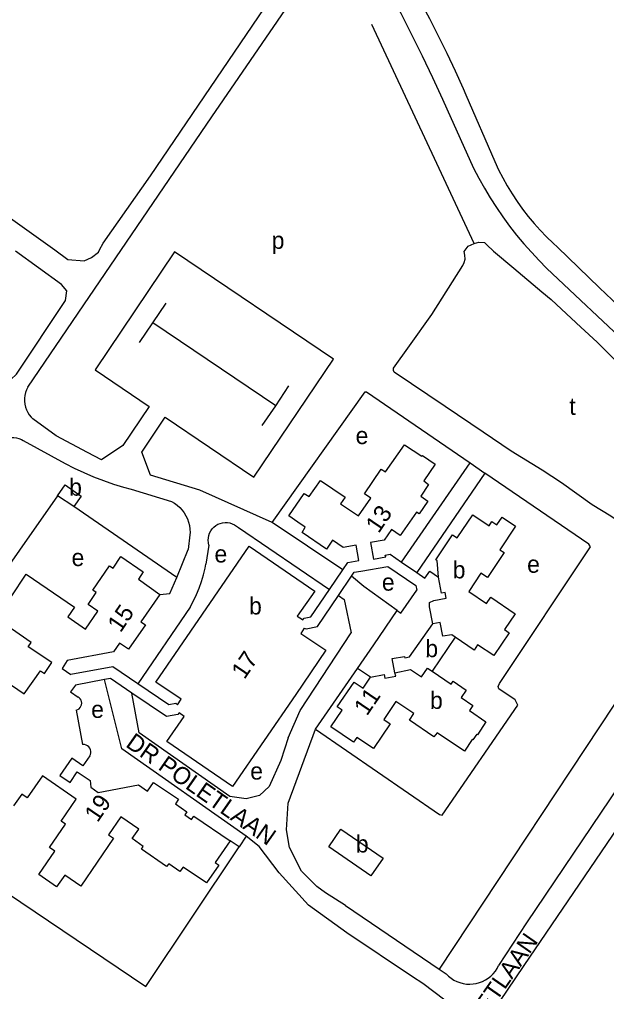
# Model space of a CAD drawing. Extents: x 158142 to 159655, y 385262 to 387204.
# Drawn here: x 159265.7 to 159402.4, y 385994 to 386220.3 of the extents above; entities that cross this region are included whole.
import ezdxf

# ---------------------------------------------------------------- set-up
doc = ezdxf.new("R2010")
doc.units = 0
for name, color, linetype in [('BLT_Basislijn', 7, 'Continuous'), ('BLT_Bebouwing', 7, 'Continuous'), ('BLT_Centroide', 7, 'Continuous'), ('BLT_Huisnummer', 7, 'Continuous'), ('BLT_Onderverdeling_panden', 7, 'Continuous'), ('BLT_Straatnaam_verkleind', 7, 'Continuous')]:
    doc.layers.add(name, color=color, linetype=linetype)

msp = doc.modelspace()

# ---------------------------------------------------------------- linework, layer by layer
at = {"layer": 'BLT_Basislijn'}
for p, q in [((159369.67, 386202.8), (159376.4, 386187.3)), ((159365.25, 386199.55), (159371.45, 386185.69)), ((159280.7, 386153.85), (159310.52, 386197.65)), ((159296.78, 386149.68), (159299.89, 386154.28)), ((159267.69, 386134.69), (159280.7, 386153.85)), ((159293.68, 386145.09), (159296.78, 386149.68)), ((159325.39, 386130.39), (159296.78, 386149.68)), ((159325.39, 386130.39), (159328.49, 386134.99)), ((159322.28, 386125.79), (159325.39, 386130.39)), ((159274.28, 386123.41), (159268.85, 386127.37)), ((159266.61, 386122.3), (159276.35, 386116.91)), ((159354.67, 386093.99), (159370.66, 386117.05)), ((159370.66, 386117.05), (159374.09, 386114.69)), ((159374.09, 386114.69), (159358.23, 386091.55)), ((159291.71, 386110.92), (159301.1, 386108.1)), ((159302.38, 386090.37), (159278.36, 386106.9)), ((159316.7, 386101.99), (159337.91, 386087.59)), ((159305.42, 386100.34), (159305, 386096.93)), ((159309.84, 386097.92), (159309.14, 386093.51)), ((159302.38, 386090.37), (159305, 386096.93)), ((159340.01, 386086.16), (159341.34, 386085.26)), ((159341.34, 386085.26), (159342.96, 386077.47)), ((159305.48, 386083.48), (159293.29, 386065.65)), ((159417.74, 386081.26), (159363.43, 385999.19)), ((159334.65, 386055.1), (159344.46, 386069.2)), ((159417.4, 386059.84), (159383.77, 386009.99)), ((159422.86, 386058.44), (159383.2, 386000)), ((159295.18, 385995.16), (159316.87, 386027.67)), ((159316.87, 386027.67), (159314.77, 386029.04)), ((159341.68, 386014.02), (159363.43, 385999.19)), ((159383.77, 386009.99), (159377.31, 386000)), ((159383.2, 386000), (159360.49, 385966.58)), ((159363.43, 385999.19), (159365.06, 385998.08))]:
    msp.add_line(p, q, dxfattribs=at)
for points in [[(159257.19, 386172.23), (159259.87, 386175.88), (159260.88, 386175.98), (159273.93, 386166.67), (159277.01, 386164.47), (159280.82, 386164.1), (159282.54, 386164.89), (159284.1, 386166.15), (159284.38, 386166.67), (159285.25, 386168.27), (159296.23, 386183.93), (159335.35, 386241.6)], [(159349.8, 386240.06), (159352.21, 386236.24), (159354.56, 386232.37), (159356.84, 386228.47), (159359.05, 386224.52), (159361.19, 386220.54), (159363.26, 386216.52), (159365.26, 386212.46), (159367.18, 386208.37), (159369.04, 386204.25), (159369.67, 386202.8)], [(159310.52, 386197.65), (159328.55, 386223.94), (159339.27, 386239.78)], [(159349.21, 386231.63), (159351.9, 386226.75), (159354.51, 386221.83), (159357.05, 386216.87), (159359.52, 386211.88), (159361.92, 386206.85), (159364.25, 386201.79), (159365.25, 386199.55)], [(159371.61, 386168.13), (159362.91, 386186.76), (159347.77, 386219.17)], [(159371.45, 386185.69), (159372.68, 386183.35), (159373.98, 386181.04), (159375.34, 386178.77), (159376.78, 386176.54), (159378.28, 386174.36), (159379.85, 386172.23), (159381.48, 386170.14), (159383.17, 386168.11), (159384.93, 386166.12), (159386.74, 386164.19), (159388.48, 386162.44)], [(159376.4, 386187.3), (159377.31, 386185.35), (159378.28, 386183.44), (159379.33, 386181.56), (159380.44, 386179.73), (159381.62, 386177.94), (159382.87, 386176.19), (159384.18, 386174.49), (159385.56, 386172.84), (159386.99, 386171.25), (159388.48, 386169.71), (159390.03, 386168.22), (159391.04, 386167.32)], [(159416.11, 386100.81), (159412.56, 386101.79), (159408.57, 386102.44), (159406.6, 386102.92), (159404.9, 386103.62), (159403.46, 386104.7), (159399.06, 386107.3), (159391.98, 386112.43), (159387.43, 386115.36), (159380.2, 386119.83), (159373.69, 386124.24), (159364.83, 386130.24), (159352.95, 386138.24), (159352.82, 386138.61), (159352.79, 386139.15), (159356.55, 386144.3), (159361.74, 386151.63), (159369, 386163.07), (159369.29, 386163.75), (159369.53, 386164.53), (159369.42, 386165.46), (159369.3, 386166.34), (159370.21, 386167.56), (159371.61, 386168.13)], [(159371.61, 386168.13), (159372.66, 386168.47), (159374.01, 386168.39), (159374.55, 386167.84), (159376.09, 386166.41), (159380.84, 386162.43), (159387.34, 386156.94), (159389.57, 386155.12), (159391.96, 386152.89), (159396.48, 386148.66), (159400.23, 386145.16), (159404.79, 386140.58)], [(159242.6, 386136.09), (159245.85, 386133.75), (159249.48, 386132.76), (159254.73, 386132.68), (159259.12, 386133.32), (159260.39, 386133.86), (159262.39, 386135.24), (159265.01, 386137.77), (159276.46, 386154.86), (159276.77, 386157.11), (159275.51, 386158.61), (159264.84, 386166.36)], [(159324.55, 386103.21), (159307.71, 386110.71), (159296.27, 386114.24), (159294.22, 386119.61), (159299.63, 386127.71), (159320.28, 386113.77), (159338.85, 386141.24), (159301.85, 386166.2), (159283.32, 386138.74), (159295.91, 386130.21), (159289.81, 386121.12), (159284.83, 386117.81), (159281.56, 386119.46), (159274.28, 386123.41)], [(159391.04, 386167.32), (159400.79, 386157.88), (159414.04, 386145.26)], [(159408.02, 386143.99), (159395.1, 386156.13), (159388.48, 386162.44)], [(159267.69, 386134.69), (159267.38, 386134.08), (159267.14, 386133.45), (159266.97, 386132.79), (159266.89, 386132.11), (159266.88, 386131.43), (159266.96, 386130.75), (159267.11, 386130.09), (159267.34, 386129.45), (159267.65, 386128.84), (159268.02, 386128.27), (159268.46, 386127.75), (159268.85, 386127.37)], [(159324.55, 386103.21), (159346.2, 386133.6), (159346.52, 386133.64), (159370.66, 386117.05)], [(159260, 386120.43), (159260.3, 386120.96), (159260.67, 386121.44), (159261.09, 386121.87), (159261.57, 386122.24), (159262.09, 386122.55), (159262.65, 386122.78), (159263.23, 386122.94), (159263.83, 386123.02), (159264.44, 386123.02), (159265.04, 386122.94), (159265.62, 386122.78), (159266.18, 386122.55), (159266.61, 386122.3)], [(159276.35, 386116.91), (159278.46, 386115.85), (159280.71, 386114.81), (159282.98, 386113.85), (159285.28, 386112.96), (159287.62, 386112.15), (159289.97, 386111.41), (159291.71, 386110.92)], [(159334.65, 386055.1), (159363.54, 386035.2), (159364.18, 386035.01), (159381.77, 386060.68), (159381.14, 386061.89), (159377.38, 386064.43), (159377.22, 386065.01), (159377.52, 386065.7), (159398.67, 386097.51), (159398.32, 386098.16), (159374.09, 386114.69)], [(159274.62, 386109.39), (159256.83, 386084.07), (159256.42, 386084.07), (159251.48, 386087.44), (159251.1, 386087.39), (159237.9, 386068.19), (159237.9, 386067.62), (159238.66, 386066.64), (159243.79, 386063.26), (159245.06, 386062.05), (159245.09, 386061.56), (159236.59, 386048.38)], [(159301.1, 386108.1), (159301.8, 386107.69), (159302.45, 386107.21), (159303.05, 386106.67), (159303.59, 386106.08), (159304.07, 386105.43), (159304.48, 386104.74), (159304.83, 386104.01), (159305.1, 386103.25), (159305.29, 386102.47), (159305.41, 386101.67), (159305.44, 386100.86), (159305.42, 386100.34)], [(159309.84, 386097.92), (159309.72, 386098.48), (159309.67, 386099.05), (159309.71, 386099.63), (159309.82, 386100.19), (159310.01, 386100.73), (159310.27, 386101.24), (159310.61, 386101.71), (159311, 386102.12), (159311.45, 386102.48), (159311.94, 386102.77), (159312.47, 386102.99), (159313.03, 386103.13), (159313.6, 386103.2), (159314.17, 386103.19), (159314.74, 386103.09), (159315.28, 386102.92), (159315.8, 386102.68), (159316.28, 386102.36), (159316.7, 386101.99)], [(159341.01, 386092.15), (159324.55, 386103.21)], [(159305.48, 386083.48), (159306.24, 386084.92), (159306.93, 386086.39), (159307.55, 386087.9), (159308.1, 386089.44), (159308.56, 386091), (159308.95, 386092.58), (159309.14, 386093.51)], [(159353.67, 386082.67), (159345.93, 386088.26), (159343.07, 386090.66)], [(159298.38, 386086.42), (159300.77, 386086.63), (159302.38, 386090.37)], [(159328.27, 386053.03), (159331.11, 386059.41), (159342.96, 386077.47)], [(159318.51, 386030.13), (159289.58, 386050.48), (159285.52, 386066.6)], [(159328.27, 386053.03), (159326.57, 386047.8), (159323.87, 386041.75), (159321.6, 386039.59), (159318.52, 386038.82), (159314.7, 386039.36), (159293.59, 386054.24), (159291.9, 386063.46)], [(159341.68, 386014.02), (159336.96, 386016.94), (159335, 386018.45), (159331.41, 386022.02), (159328.64, 386027.53), (159327.92, 386031.63), (159328.32, 386037.8), (159334.65, 386055.1)], [(159236.59, 386048.38), (159233.66, 386044.64), (159263.45, 386024.81), (159259.49, 386019.16), (159295.18, 385995.16)], [(159318.51, 386030.13), (159316.87, 386027.67)], [(159326.2, 386021.62), (159321.52, 386027.74), (159318.51, 386030.13)], [(159364.77, 385991.98), (159359.67, 385995.81), (159357.27, 385997.38), (159341.92, 386007.64), (159333.04, 386014.11), (159326.2, 386021.62)], [(159365.06, 385998.08), (159365.62, 385997.54), (159366.22, 385997.06), (159366.87, 385996.64), (159367.56, 385996.3), (159368.29, 385996.03), (159369.03, 385995.83), (159369.8, 385995.71), (159370.57, 385995.68), (159371.34, 385995.72), (159372.1, 385995.84), (159372.84, 385996.04), (159373.57, 385996.32), (159374.25, 385996.67), (159374.9, 385997.08), (159375.5, 385997.57), (159376.05, 385998.11), (159376.54, 385998.71), (159376.97, 385999.35), (159377.31, 386000)]]:
    msp.add_lwpolyline(points, dxfattribs=at)
at = {"layer": 'BLT_Bebouwing'}
for p, q in [((159278.36, 386106.9), (159274.62, 386109.39)), ((159354.67, 386093.99), (159358.23, 386091.55)), ((159337.91, 386087.59), (159341.01, 386092.15)), ((159340.01, 386086.16), (159343.07, 386090.66)), ((159358.23, 386091.55), (159360.15, 386090.24)), ((159331.64, 386080.57), (159331.67, 386080.44)), ((159367.19, 386076.5), (159361.79, 386068.57)), ((159344.46, 386069.2), (159348.23, 386074.72)), ((159277.63, 386063.76), (159279.42, 386062.54)), ((159278.96, 386059.5), (159280.41, 386051.49)), ((159282.08, 386048.83), (159280.47, 386046.49))]:
    msp.add_line(p, q, dxfattribs=at)
for points in [[(159330.54, 386103.29), (159328.43, 386104.75), (159332.03, 386109.98), (159333.19, 386109.21), (159335.8, 386113.01), (159341.54, 386109.07), (159340.47, 386107.55), (159344.67, 386104.72), (159347.56, 386108.88), (159346.06, 386109.9), (159349.99, 386115.64), (159350.99, 386114.96), (159355.38, 386121.31), (159359.43, 386118.64), (159359.56, 386118.8), (159362.52, 386116.78), (159359.88, 386112.88), (159361, 386112.06), (159359.19, 386109.35), (159360.84, 386108.18), (159358.78, 386105.2), (159358.15, 386105.62), (159354.39, 386100.18), (159352.38, 386101.59), (159350.66, 386099.08), (159347.5, 386098.55)], [(159274.62, 386109.39), (159276.38, 386111.95), (159280.1, 386109.33), (159278.36, 386106.9)], [(159363.32, 386090.45), (159362.96, 386094.34), (159362.7, 386094.52), (159366.6, 386100.31), (159367.66, 386099.59), (159371.3, 386104.98), (159375.09, 386102.42), (159375.76, 386103.43), (159376.87, 386102.67), (159378.1, 386104.47), (159381.25, 386102.35), (159377.56, 386096.85), (159378.57, 386096.17), (159374.68, 386090.38), (159373.18, 386091.39), (159370.34, 386087.16), (159374.49, 386084.32), (159375.48, 386085.83), (159381.17, 386081.95), (159378.68, 386078.24), (159379.77, 386077.51), (159376.2, 386072.19), (159372.42, 386074.73), (159371.57, 386073.47), (159367.19, 386076.5)], [(159344.16, 386097.89), (159341.12, 386097.34), (159338.63, 386099.05), (159337.2, 386097.02), (159331.52, 386100.9), (159332.29, 386102.07), (159330.54, 386103.29)], [(159302.53, 386060.76), (159303.35, 386062.02), (159297.45, 386065.99), (159319.25, 386097.72)], [(159319.25, 386097.72), (159334.52, 386087.24), (159330.43, 386081.4), (159331.64, 386080.57)], [(159341.01, 386092.15), (159342.19, 386093.87), (159344.79, 386094.36), (159344.16, 386097.89)], [(159347.5, 386098.55), (159348.15, 386094.69), (159351.04, 386095.2), (159350.92, 386095.61), (159352.04, 386095.79), (159354.67, 386093.99)], [(159263.79, 386085.92), (159267.32, 386091.16), (159278.51, 386083.48), (159276.96, 386081.24), (159281.13, 386078.37), (159283.99, 386082.54), (159281.73, 386084.09), (159283.56, 386086.86), (159282.84, 386087.4), (159286.72, 386093.11), (159287.51, 386092.58), (159289.32, 386095.28), (159294.51, 386091.71), (159293.41, 386090.03), (159298.38, 386086.42)], [(159343.07, 386090.66), (159343.7, 386091.59), (159345.24, 386091.86), (159351.47, 386092.96), (159357.99, 386088.53), (159358.22, 386087.41)], [(159360.15, 386090.24), (159361.26, 386091.86), (159363.32, 386090.45)], [(159298.38, 386086.42), (159294.02, 386080.05), (159295.04, 386079.34), (159291.09, 386073.68), (159289.05, 386075.07), (159287.64, 386073.08), (159276.87, 386071.04), (159275.67, 386069.23), (159277.67, 386067.81)], [(159331.67, 386080.44), (159332, 386080.92), (159333.58, 386081.23), (159337.91, 386087.59)], [(159332.01, 386078.61), (159332.46, 386078.41), (159335.11, 386078.94), (159340.01, 386086.16)], [(159353.67, 386082.67), (159354.56, 386082.06), (159358.22, 386087.41)], [(159348.23, 386074.72), (159353.67, 386082.67)], [(159262.39, 386066.32), (159266.82, 386063.33), (159270.59, 386068.68), (159271.54, 386068.04), (159273.23, 386070.6), (159267.78, 386074.27), (159268.46, 386075.27), (159262.08, 386079.66)], [(159332.01, 386078.61), (159331.22, 386077.34), (159337.1, 386073.46), (159330.05, 386063.16)], [(159293.29, 386065.65), (159287.5, 386069.59), (159277.67, 386067.81)], [(159361.79, 386068.57), (159366.27, 386065.55), (159366.71, 386066.22), (159369.72, 386064.16), (159368.6, 386062.46), (159371.29, 386060.57), (159370.51, 386059.44), (159374.35, 386056.76), (159372.36, 386053.78), (159372.22, 386053.88), (159371.28, 386052.58), (159371.17, 386052.65), (159369.38, 386049.95), (159362.99, 386054.24), (159362.24, 386053.27), (159356.52, 386057.16), (159357.54, 386058.69), (159353.37, 386061.54), (159350.55, 386057.34), (159352.05, 386056.33), (159348.13, 386050.57), (159344.31, 386053.12), (159343.5, 386052), (159338.23, 386055.58), (159340.9, 386059.52), (159339.73, 386060.28), (159343.67, 386066.03), (159345.73, 386064.62), (159347.45, 386067.15)], [(159347.45, 386067.15), (159344.46, 386069.2)], [(159353.17, 386068.21), (159356.81, 386068.93), (159359.38, 386067.23), (159360.76, 386069.27), (159361.79, 386068.57)], [(159285.52, 386066.6), (159278.77, 386065.34), (159277.63, 386063.76)], [(159291.9, 386063.46), (159286.91, 386066.86), (159285.52, 386066.6)], [(159302.92, 386058.89), (159302.64, 386058.51), (159299.95, 386057.98), (159291.9, 386063.46)], [(159302.53, 386060.76), (159302.16, 386061.04), (159300.53, 386060.72), (159293.29, 386065.65)], [(159278.96, 386059.5), (159279.3, 386059.63), (159279.6, 386059.83), (159279.86, 386060.09), (159280.05, 386060.4), (159280.17, 386060.74), (159280.22, 386061.1), (159280.18, 386061.47), (159280.07, 386061.81), (159279.88, 386062.13), (159279.63, 386062.39), (159279.42, 386062.54)], [(159330.05, 386063.16), (159315.37, 386041.72), (159300.08, 386052.17), (159304.07, 386058.01), (159302.92, 386058.89)], [(159282.08, 386048.83), (159282.24, 386049.17), (159282.32, 386049.54), (159282.32, 386049.91), (159282.24, 386050.28), (159282.09, 386050.62), (159281.87, 386050.92), (159281.59, 386051.17), (159281.26, 386051.36), (159280.9, 386051.47), (159280.52, 386051.5), (159280.41, 386051.49)], [(159280.47, 386046.49), (159277.89, 386048.33), (159275.11, 386044.3), (159277.51, 386042.61), (159279.19, 386045.1), (159282.16, 386043.08)], [(159314.77, 386029.04), (159311.3, 386023.99), (159312.18, 386023.39), (159309.25, 386019.25), (159303.84, 386022.94), (159303.11, 386021.91), (159300.48, 386023.72), (159299.98, 386023.05), (159294.11, 386027.11), (159294.56, 386027.73), (159291.98, 386029.58), (159293.49, 386031.79), (159289.35, 386034.67), (159286.49, 386030.49), (159287.63, 386029.66), (159280.03, 386018.47), (159276.27, 386021.08), (159274.35, 386018.34), (159270.24, 386021.21), (159273.95, 386026.65), (159272.7, 386027.51), (159276.43, 386032.95), (159275.41, 386033.66), (159278.92, 386038.79), (159271.08, 386044.23), (159267.53, 386039.05), (159266.25, 386039.9), (159264.34, 386037.18)], [(159282.16, 386043.08), (159282.32, 386041.52), (159284.07, 386040.32), (159293.44, 386042.08)], [(159293.44, 386042.08), (159295.55, 386040.63), (159296.96, 386042.66), (159302.74, 386038.75), (159302.05, 386037.7), (159304.73, 386035.83), (159304.21, 386035.09), (159305.76, 386034.03), (159306.3, 386034.79), (159314.77, 386029.04)]]:
    msp.add_lwpolyline(points, dxfattribs=at)
msp.add_lwpolyline([(159337.73, 386027.66), (159340.54, 386031.78), (159350.39, 386025.05), (159347.58, 386020.93)], close=True, dxfattribs=at)
at = {"layer": 'BLT_Onderverdeling_panden'}
for points in [[(159362, 386079.6), (159361.24, 386083.56), (159361.24, 386083.56), (159361.24, 386084.59), (159362.25, 386085.06), (159365.08, 386085.59), (159364.84, 386086.93), (159364.03, 386086.77), (159363.32, 386090.45)], [(159353.17, 386068.21), (159352.52, 386071.5), (159355.36, 386072.02), (159355.44, 386071.66), (159356.57, 386071.89), (159362, 386079.6)], [(159367.19, 386076.5), (159366.42, 386077.03), (159364.3, 386076.69), (159363.67, 386079.92), (159362, 386079.6)], [(159347.45, 386067.15), (159350.65, 386067.76), (159350.82, 386066.93), (159353.33, 386067.39), (159353.17, 386068.21)]]:
    msp.add_lwpolyline(points, dxfattribs=at)

# ---------------------------------------------------------------- texts
at = {"layer": 'BLT_Centroide'}
for s, p in [('p', (159324.45, 386166.91)), ('t', (159393.76, 386128.25)), ('e', (159344, 386121.45)), ('b', (159277.3, 386109.44)), ('e', (159277.86, 386093.05)), ('e', (159311.14, 386093.88)), ('b', (159366.61, 386090.18)), ('e', (159383.94, 386091.49)), ('e', (159350.12, 386087.32)), ('b', (159319.19, 386081.77)), ('b', (159360.23, 386071.83)), ('b', (159361.32, 386059.78)), ('e', (159282.43, 386057.68)), ('e', (159319.46, 386043.32)), ('b', (159344.06, 386026.34))]:
    msp.add_text(s, height=4, dxfattribs=at).set_placement(p)
at = {"layer": 'BLT_Huisnummer'}
for s, p in [('13', (159349.36, 386100.49)), ('15', (159289.26, 386077.36)), ('17', (159318.1, 386066.47)), ('11', (159346.64, 386057.98)), ('19', (159283.91, 386033.15))]:
    msp.add_text(s, height=4, rotation=55.7112, dxfattribs=at).set_placement(p)
at = {"layer": 'BLT_Straatnaam_verkleind'}
for rotation, p in [(325.007, (159290.24, 386051.14)), (55.2331, (159363.45, 385972.25))]:
    msp.add_text('DR POLETLAAN', height=4, rotation=rotation, dxfattribs=at).set_placement(p)

doc.saveas('drawing.dxf')
